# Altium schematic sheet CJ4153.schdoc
size 127 x 101 mm
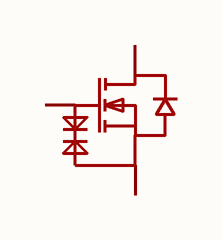
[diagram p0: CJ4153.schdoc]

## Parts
Q?  cj4153  [SOT-523-3_L1.6-W0.8-P1.00-LS1.6-BR]  (value not drawn)

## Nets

Not connected (* = marked no-connect by the designer): Q? 1(G) 2(S) 3(D)

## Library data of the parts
Q? = cj4153: 数量:1个N沟道;漏源电压(Vdss):20V;连续漏极电流(Id):915mA;导通电阻(RDS(on)):570mΩ@4.5V;耗散功率(Pd):150mW;阈值电压(Vgs(th)):1.1V;; Manufacturer: CJ(江苏长电/长晶); AddInBom: yes; ModelId: 3e7fadd59d8d474faa89c2c7e0676879; ModelName: SOT-523-3P_L1.6-W0.8-H0.9-LS1.6-P0.50; ModelTransform: 63.48633,62.992,0,180,0,0,0,0,0; Number: 1个N沟道; Drain to Source Voltage: 20V; Current - Continuous Drain(Id): 915mA; Pd - Power Dissipation: 150mW; Gate Threshold Voltage (Vgs(th)): 1.1V; Gate Charge(Qg): 1.82nC; Input Capacitance(Ciss): 110pF; Reverse Transfer Capacitance (Crss@Vds): 12pF; Type: N沟道; Output Capacitance(Coss): 16pF; Vgs: ±6V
